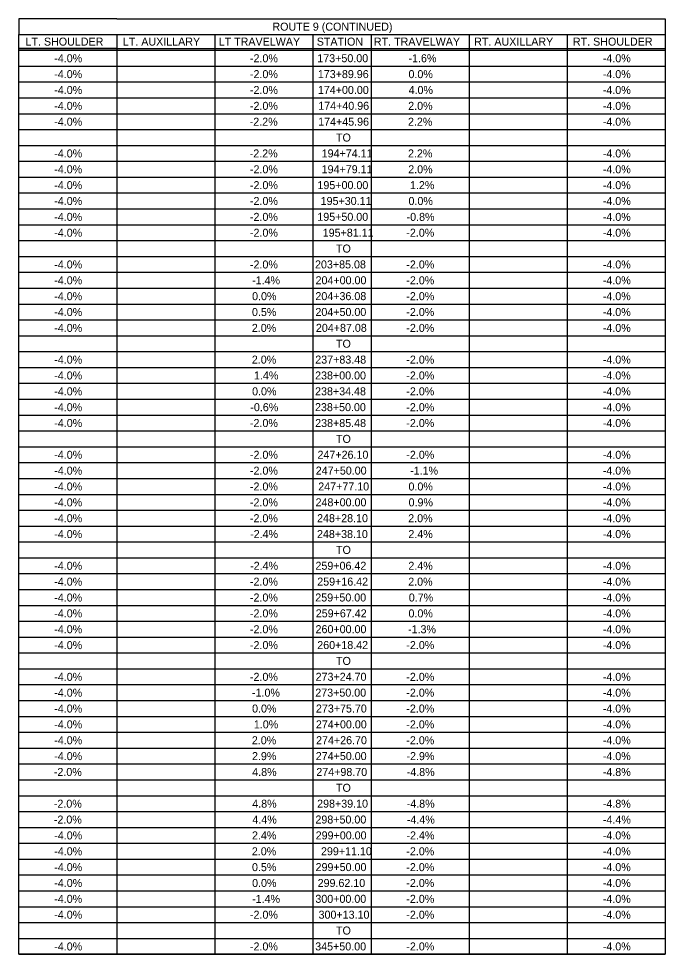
# Model space of a CAD drawing. Extents: x -15319374 to 1762012, y 465773 to 3693661.
# Drawn here: x -15319121 to -15318878.5, y 3690631.6 to 3690982.2 of the extents above; entities that cross this region are included whole.
import ezdxf

# ---------------------------------------------------------------- set-up
doc = ezdxf.new("R2010")
doc.units = 0
doc.layers.add('BORDER', color=7, linetype='Continuous')
doc.layers.add('DIMENSIONS', color=7, linetype='Continuous')

msp = doc.modelspace()

# ---------------------------------------------------------------- linework, layer by layer
at = {"layer": 'BORDER'}
for p, q in [((-15319084.25, 3690976.24), (-15319084.25, 3690631.63)), ((-15319047.48, 3690976.24), (-15319047.48, 3690631.63)), ((-15319010.71, 3690976.24), (-15319010.71, 3690631.63)), ((-15318988.84, 3690976.24), (-15318988.84, 3690631.63)), ((-15318952.07, 3690976.24), (-15318952.07, 3690631.63)), ((-15318915.3, 3690976.24), (-15318915.3, 3690631.63)), ((-15319084.25, 3690970.96), (-15319121.02, 3690970.96)), ((-15319121.02, 3690970.36), (-15318878.53, 3690970.36)), ((-15319084.25, 3690970.36), (-15319121.02, 3690970.36)), ((-15319084.25, 3690970.96), (-15318878.53, 3690970.96)), ((-15319084.25, 3690970.36), (-15318878.53, 3690970.36)), ((-15319121.02, 3690964.42), (-15318878.53, 3690964.42)), ((-15319121.02, 3690958.48), (-15318878.53, 3690958.48)), ((-15319121.02, 3690952.54), (-15318878.53, 3690952.54)), ((-15319121.02, 3690946.59), (-15318878.53, 3690946.59)), ((-15319121.02, 3690940.65), (-15318878.53, 3690940.65)), ((-15319121.02, 3690934.71), (-15318878.53, 3690934.71)), ((-15319121.02, 3690928.76), (-15318878.53, 3690928.76)), ((-15319121.02, 3690922.82), (-15318878.53, 3690922.82)), ((-15319121.02, 3690916.88), (-15318878.53, 3690916.88)), ((-15319121.02, 3690910.94), (-15318878.53, 3690910.94)), ((-15319121.02, 3690904.99), (-15318878.53, 3690904.99)), ((-15319121.02, 3690899.05), (-15318878.53, 3690899.05)), ((-15319121.02, 3690893.11), (-15318878.53, 3690893.11)), ((-15319121.02, 3690887.17), (-15318878.53, 3690887.17)), ((-15319121.02, 3690881.22), (-15318878.53, 3690881.22)), ((-15319121.02, 3690875.28), (-15318878.53, 3690875.28)), ((-15319121.02, 3690869.34), (-15318878.53, 3690869.34)), ((-15319121.02, 3690863.39), (-15318878.53, 3690863.39)), ((-15319121.02, 3690857.45), (-15318878.53, 3690857.45)), ((-15319121.02, 3690851.51), (-15318878.53, 3690851.51)), ((-15319121.02, 3690845.57), (-15318878.53, 3690845.57)), ((-15319121.02, 3690839.62), (-15318878.53, 3690839.62)), ((-15319121.02, 3690833.68), (-15318878.53, 3690833.68)), ((-15319121.02, 3690827.74), (-15318878.53, 3690827.74)), ((-15319121.02, 3690821.8), (-15318878.53, 3690821.8)), ((-15319121.02, 3690815.85), (-15318878.53, 3690815.85)), ((-15319121.02, 3690809.91), (-15318878.53, 3690809.91)), ((-15319121.02, 3690803.97), (-15318878.53, 3690803.97)), ((-15319121.02, 3690798.02), (-15318878.53, 3690798.02)), ((-15319121.02, 3690792.08), (-15318878.53, 3690792.08)), ((-15319121.02, 3690786.14), (-15318878.53, 3690786.14)), ((-15319121.02, 3690780.2), (-15318878.53, 3690780.2)), ((-15319121.02, 3690774.25), (-15318878.53, 3690774.25)), ((-15319121.02, 3690768.31), (-15318878.53, 3690768.31)), ((-15319121.02, 3690762.37), (-15318878.53, 3690762.37)), ((-15319121.02, 3690756.43), (-15318878.53, 3690756.43)), ((-15319121.02, 3690750.48), (-15318878.53, 3690750.48)), ((-15319121.02, 3690744.54), (-15318878.53, 3690744.54)), ((-15319121.02, 3690738.6), (-15318878.53, 3690738.6)), ((-15319121.02, 3690732.66), (-15318878.53, 3690732.66)), ((-15319121.02, 3690726.71), (-15318878.53, 3690726.71)), ((-15319121.02, 3690720.77), (-15318878.53, 3690720.77)), ((-15319121.02, 3690714.83), (-15318878.53, 3690714.83)), ((-15319121.02, 3690708.88), (-15318878.53, 3690708.88)), ((-15319121.02, 3690702.94), (-15318878.53, 3690702.94)), ((-15319121.02, 3690697), (-15318878.53, 3690697)), ((-15319121.02, 3690691.06), (-15318878.53, 3690691.06)), ((-15319121.02, 3690685.11), (-15318878.53, 3690685.11)), ((-15319121.02, 3690679.17), (-15318878.53, 3690679.17)), ((-15319121.02, 3690673.23), (-15318878.53, 3690673.23)), ((-15319121.02, 3690667.29), (-15318878.53, 3690667.29)), ((-15319121.02, 3690661.34), (-15318878.53, 3690661.34)), ((-15319121.02, 3690655.4), (-15318878.53, 3690655.4)), ((-15319121.02, 3690649.46), (-15318878.53, 3690649.46)), ((-15319121.02, 3690643.51), (-15318878.53, 3690643.51)), ((-15319121.02, 3690637.57), (-15318878.53, 3690637.57)), ((-15319121.02, 3690631.63), (-15318878.53, 3690631.63))]:
    msp.add_line(p, q, dxfattribs=at)
for points in [[(-15319084.25, 3690982.18), (-15319121.02, 3690982.18), (-15319121.02, 3690976.24)], [(-15319084.25, 3690982.18), (-15318915.3, 3690982.18)], [(-15318915.3, 3690982.18), (-15318878.53, 3690982.18), (-15318878.53, 3690976.24)]]:
    msp.add_lwpolyline(points, dxfattribs=at)
msp.add_lwpolyline([(-15319121.02, 3690976.24), (-15318878.53, 3690976.24), (-15318878.53, 3690631.63), (-15319121.02, 3690631.63)], close=True, dxfattribs=at)

# ---------------------------------------------------------------- texts
at = {"layer": 'DIMENSIONS'}
for s, p in [('ROUTE 9 (CONTINUED)', (-15319025.87, 3690977.71)), ('LT. SHOULDER', (-15319118.46, 3690972.1)), ('LT. AUXILLARY', (-15319081.96, 3690972.1)), ('LT TRAVELWAY', (-15319046.03, 3690972.1)), ('STATION', (-15319009.25, 3690972.1)), ('RT. TRAVELWAY', (-15318987.82, 3690972.1)), ('RT. AUXILLARY', (-15318950.21, 3690972.1)), ('RT. SHOULDER', (-15318913.18, 3690972.1)), ('-4.0%', (-15319107.68, 3690965.86)), ('-2.0%', (-15319034.29, 3690965.86)), ('173+50.00', (-15319009.03, 3690965.88)), ('-1.6%', (-15318974.84, 3690965.86)), ('-4.0%', (-15318901.97, 3690965.86)), ('-4.0%', (-15319107.68, 3690959.92)), ('-2.0%', (-15319034.29, 3690959.92)), ('173+89.96', (-15319008.84, 3690959.93)), ('0.0%', (-15318974.84, 3690959.92)), ('-4.0%', (-15318901.97, 3690959.92)), ('-4.0%', (-15319107.68, 3690953.97)), ('-2.0%', (-15319034.29, 3690953.97)), ('174+00.00', (-15319008.82, 3690953.99)), ('4.0%', (-15318974.8, 3690953.97)), ('-4.0%', (-15318901.97, 3690953.97)), ('-4.0%', (-15319107.68, 3690948.03)), ('-2.0%', (-15319034.29, 3690948.03)), ('174+40.96', (-15319008.68, 3690948.05)), ('2.0%', (-15318974.94, 3690948.03)), ('-4.0%', (-15318901.97, 3690948.03)), ('-4.0%', (-15319107.68, 3690942.09)), ('-2.2%', (-15319034.38, 3690942.09)), ('174+45.96', (-15319008.72, 3690942.1)), ('2.2%', (-15318975.03, 3690942.09)), ('-4.0%', (-15318901.97, 3690942.09)), ('TO', (-15319002.02, 3690936.16)), ('-4.0%', (-15319107.68, 3690930.2)), ('-2.2%', (-15319034.38, 3690930.2)), ('194+74.11', (-15319007.4, 3690930.22)), ('2.2%', (-15318975.03, 3690930.2)), ('-4.0%', (-15318901.97, 3690930.2)), ('-4.0%', (-15319107.68, 3690924.26)), ('-2.0%', (-15319034.29, 3690924.26)), ('194+79.11', (-15319007.4, 3690924.28)), ('2.0%', (-15318974.94, 3690924.26)), ('-4.0%', (-15318901.97, 3690924.26)), ('-4.0%', (-15319107.68, 3690918.32)), ('-2.0%', (-15319034.29, 3690918.32)), ('195+00.00', (-15319008.98, 3690918.33)), ('1.2%', (-15318974.28, 3690918.32)), ('-4.0%', (-15318901.97, 3690918.32)), ('-4.0%', (-15319107.68, 3690912.38)), ('-2.0%', (-15319034.29, 3690912.38)), ('195+30.11', (-15319007.78, 3690912.39)), ('0.0%', (-15318974.84, 3690912.38)), ('-4.0%', (-15318901.97, 3690912.38)), ('-4.0%', (-15319107.68, 3690906.43)), ('-2.0%', (-15319034.29, 3690906.43)), ('195+50.00', (-15319009.03, 3690906.45)), ('-0.8%', (-15318975.55, 3690906.43)), ('-4.0%', (-15318901.97, 3690906.43)), ('-4.0%', (-15319107.68, 3690900.49)), ('-2.0%', (-15319034.29, 3690900.49)), ('195+81.11', (-15319007, 3690900.51)), ('-2.0%', (-15318975.65, 3690900.49)), ('-4.0%', (-15318901.97, 3690900.49)), ('TO', (-15319002.02, 3690894.56)), ('-4.0%', (-15319107.68, 3690888.6)), ('-2.0%', (-15319034.29, 3690888.6)), ('203+85.08', (-15319009.89, 3690888.62)), ('-2.0%', (-15318975.65, 3690888.6)), ('-4.0%', (-15318901.97, 3690888.6)), ('-4.0%', (-15319107.68, 3690882.66)), ('-1.4%', (-15319033.49, 3690882.66)), ('204+00.00', (-15319009.69, 3690882.68)), ('-2.0%', (-15318975.65, 3690882.66)), ('-4.0%', (-15318901.97, 3690882.66)), ('-4.0%', (-15319107.68, 3690876.72)), ('0.0%', (-15319033.49, 3690876.72)), ('204+36.08', (-15319009.75, 3690876.73)), ('-2.0%', (-15318975.65, 3690876.72)), ('-4.0%', (-15318901.97, 3690876.72)), ('-4.0%', (-15319107.68, 3690870.78)), ('0.5%', (-15319033.53, 3690870.78)), ('204+50.00', (-15319009.74, 3690870.79)), ('-2.0%', (-15318975.65, 3690870.78)), ('-4.0%', (-15318901.97, 3690870.78)), ('-4.0%', (-15319107.68, 3690864.83)), ('2.0%', (-15319033.58, 3690864.83)), ('204+87.08', (-15319009.56, 3690864.85)), ('-2.0%', (-15318975.65, 3690864.83)), ('-4.0%', (-15318901.97, 3690864.83)), ('TO', (-15319002.02, 3690858.91)), ('-4.0%', (-15319107.68, 3690852.95)), ('2.0%', (-15319033.58, 3690852.95)), ('237+83.48', (-15319009.8, 3690852.96)), ('-2.0%', (-15318975.65, 3690852.95)), ('-4.0%', (-15318901.97, 3690852.95)), ('-4.0%', (-15319107.68, 3690847.01)), ('1.4%', (-15319032.78, 3690847.01)), ('238+00.00', (-15319009.86, 3690847.02)), ('-2.0%', (-15318975.65, 3690847.01)), ('-4.0%', (-15318901.97, 3690847.01)), ('-4.0%', (-15319107.68, 3690841.06)), ('0.0%', (-15319033.49, 3690841.06)), ('238+34.48', (-15319009.87, 3690841.08)), ('-2.0%', (-15318975.65, 3690841.06)), ('-4.0%', (-15318901.97, 3690841.06)), ('-4.0%', (-15319107.68, 3690835.12)), ('-0.6%', (-15319034.15, 3690835.12)), ('238+50.00', (-15319009.9, 3690835.14)), ('-2.0%', (-15318975.65, 3690835.12)), ('-4.0%', (-15318901.97, 3690835.12)), ('-4.0%', (-15319107.68, 3690829.18)), ('-2.0%', (-15319034.29, 3690829.18)), ('238+85.48', (-15319009.84, 3690829.19)), ('-2.0%', (-15318975.65, 3690829.18)), ('-4.0%', (-15318901.97, 3690829.18)), ('TO', (-15319002.02, 3690823.25)), ('-4.0%', (-15319107.68, 3690817.29)), ('-2.0%', (-15319034.29, 3690817.29)), ('247+26.10', (-15319008.96, 3690817.31)), ('-2.0%', (-15318975.65, 3690817.29)), ('-4.0%', (-15318901.97, 3690817.29)), ('-4.0%', (-15319107.68, 3690811.35)), ('-2.0%', (-15319034.29, 3690811.35)), ('247+50.00', (-15319009.62, 3690811.37)), ('-1.1%', (-15318974.23, 3690811.35)), ('-4.0%', (-15318901.97, 3690811.35)), ('-4.0%', (-15319107.68, 3690805.41)), ('-2.0%', (-15319034.29, 3690805.41)), ('247+77.10', (-15319008.68, 3690805.42)), ('0.0%', (-15318974.84, 3690805.41)), ('-4.0%', (-15318901.97, 3690805.41)), ('-4.0%', (-15319107.68, 3690799.46)), ('-2.0%', (-15319034.29, 3690799.46)), ('248+00.00', (-15319009.69, 3690799.48)), ('0.9%', (-15318974.8, 3690799.46)), ('-4.0%', (-15318901.97, 3690799.46)), ('-4.0%', (-15319107.68, 3690793.52)), ('-2.0%', (-15319034.29, 3690793.52)), ('248+28.10', (-15319009.12, 3690793.54)), ('2.0%', (-15318974.94, 3690793.52)), ('-4.0%', (-15318901.97, 3690793.52)), ('-4.0%', (-15319107.68, 3690787.58)), ('-2.4%', (-15319034.24, 3690787.58)), ('248+38.10', (-15319009.15, 3690787.59)), ('2.4%', (-15318974.89, 3690787.58)), ('-4.0%', (-15318901.97, 3690787.58)), ('TO', (-15319002.02, 3690781.65)), ('-4.0%', (-15319107.68, 3690775.69)), ('-2.4%', (-15319034.24, 3690775.69)), ('259+06.42', (-15319009.73, 3690775.71)), ('2.4%', (-15318974.89, 3690775.69)), ('-4.0%', (-15318901.97, 3690775.69)), ('-4.0%', (-15319107.68, 3690769.75)), ('-2.0%', (-15319034.29, 3690769.75)), ('259+16.42', (-15319009.06, 3690769.77)), ('2.0%', (-15318974.94, 3690769.75)), ('-4.0%', (-15318901.97, 3690769.75)), ('-4.0%', (-15319107.68, 3690763.81)), ('-2.0%', (-15319034.29, 3690763.81)), ('259+50.00', (-15319009.79, 3690763.82)), ('0.7%', (-15318974.73, 3690763.81)), ('-4.0%', (-15318901.97, 3690763.81)), ('-4.0%', (-15319107.68, 3690757.86)), ('-2.0%', (-15319034.29, 3690757.86)), ('259+67.42', (-15319009.61, 3690757.88)), ('0.0%', (-15318974.84, 3690757.86)), ('-4.0%', (-15318901.97, 3690757.86)), ('-4.0%', (-15319107.68, 3690751.92)), ('-2.0%', (-15319034.29, 3690751.92)), ('260+00.00', (-15319009.69, 3690751.94)), ('-1.3%', (-15318975.01, 3690751.92)), ('-4.0%', (-15318901.97, 3690751.92)), ('-4.0%', (-15319107.68, 3690745.98)), ('-2.0%', (-15319034.29, 3690745.98)), ('260+18.42', (-15319009.06, 3690746)), ('-2.0%', (-15318975.65, 3690745.98)), ('-4.0%', (-15318901.97, 3690745.98)), ('TO', (-15319002.02, 3690740.05)), ('-4.0%', (-15319107.68, 3690734.09)), ('-2.0%', (-15319034.29, 3690734.09)), ('273+24.70', (-15319009.67, 3690734.11)), ('-2.0%', (-15318975.65, 3690734.09)), ('-4.0%', (-15318901.97, 3690734.09)), ('-4.0%', (-15319107.68, 3690728.15)), ('-1.0%', (-15319033.53, 3690728.15)), ('273+50.00', (-15319009.79, 3690728.17)), ('-2.0%', (-15318975.65, 3690728.15)), ('-4.0%', (-15318901.97, 3690728.15)), ('-4.0%', (-15319107.68, 3690722.21)), ('0.0%', (-15319033.49, 3690722.21)), ('273+75.70', (-15319009.55, 3690722.22)), ('-2.0%', (-15318975.65, 3690722.21)), ('-4.0%', (-15318901.97, 3690722.21)), ('-4.0%', (-15319107.68, 3690716.27)), ('1.0%', (-15319032.83, 3690716.27)), ('274+00.00', (-15319009.57, 3690716.28)), ('-2.0%', (-15318975.65, 3690716.27)), ('-4.0%', (-15318901.97, 3690716.27)), ('-4.0%', (-15319107.68, 3690710.32)), ('2.0%', (-15319033.58, 3690710.32)), ('274+26.70', (-15319009.5, 3690710.34)), ('-2.0%', (-15318975.65, 3690710.32)), ('-4.0%', (-15318901.97, 3690710.32)), ('-4.0%', (-15319107.68, 3690704.38)), ('2.9%', (-15319033.53, 3690704.38)), ('274+50.00', (-15319009.62, 3690704.4)), ('-2.9%', (-15318975.6, 3690704.38)), ('-4.0%', (-15318901.97, 3690704.38)), ('-2.0%', (-15319107.83, 3690698.44)), ('4.8%', (-15319033.44, 3690698.44)), ('274+98.70', (-15319009.41, 3690698.45)), ('-4.8%', (-15318975.51, 3690698.44)), ('-4.8%', (-15318901.97, 3690698.44)), ('TO', (-15319002.02, 3690692.51)), ('-2.0%', (-15319107.83, 3690686.55)), ('4.8%', (-15319033.44, 3690686.55)), ('298+39.10', (-15319009.1, 3690686.57)), ('-4.8%', (-15318975.51, 3690686.55)), ('-4.8%', (-15318901.97, 3690686.55)), ('-2.0%', (-15319107.83, 3690680.61)), ('4.4%', (-15319033.39, 3690680.61)), ('298+50.00', (-15319009.74, 3690680.63)), ('-4.4%', (-15318975.46, 3690680.61)), ('-4.4%', (-15318901.92, 3690680.61)), ('-4.0%', (-15319107.68, 3690674.67)), ('2.4%', (-15319033.53, 3690674.67)), ('299+00.00', (-15319009.64, 3690674.68)), ('-2.4%', (-15318975.6, 3690674.67)), ('-4.0%', (-15318901.97, 3690674.67)), ('-4.0%', (-15319107.68, 3690668.72)), ('2.0%', (-15319033.58, 3690668.72)), ('299+11.10', (-15319007.66, 3690668.74)), ('-2.0%', (-15318975.65, 3690668.72)), ('-4.0%', (-15318901.97, 3690668.72)), ('-4.0%', (-15319107.68, 3690662.78)), ('0.5%', (-15319033.53, 3690662.78)), ('299+50.00', (-15319009.69, 3690662.8)), ('-2.0%', (-15318975.65, 3690662.78)), ('-4.0%', (-15318901.97, 3690662.78)), ('-4.0%', (-15319107.68, 3690656.84)), ('0.0%', (-15319033.49, 3690656.84)), ('299.62.10', (-15319008.91, 3690656.85)), ('-2.0%', (-15318975.65, 3690656.84)), ('-4.0%', (-15318901.97, 3690656.84)), ('-4.0%', (-15319107.68, 3690650.9)), ('-1.4%', (-15319033.49, 3690650.9)), ('300+00.00', (-15319009.76, 3690650.91)), ('-2.0%', (-15318975.65, 3690650.9)), ('-4.0%', (-15318901.97, 3690650.9)), ('-4.0%', (-15319107.68, 3690644.95)), ('-2.0%', (-15319034.29, 3690644.95)), ('300+13.10', (-15319008.56, 3690644.97)), ('-2.0%', (-15318975.65, 3690644.95)), ('-4.0%', (-15318901.97, 3690644.95)), ('TO', (-15319002.02, 3690639.03)), ('-4.0%', (-15319107.68, 3690633.07)), ('-2.0%', (-15319034.29, 3690633.07)), ('345+50.00', (-15319009.81, 3690633.08)), ('-2.0%', (-15318975.65, 3690633.07)), ('-4.0%', (-15318901.97, 3690633.07))]:
    msp.add_text(s, height=3, dxfattribs=at).set_placement(p)

doc.saveas('drawing.dxf')
